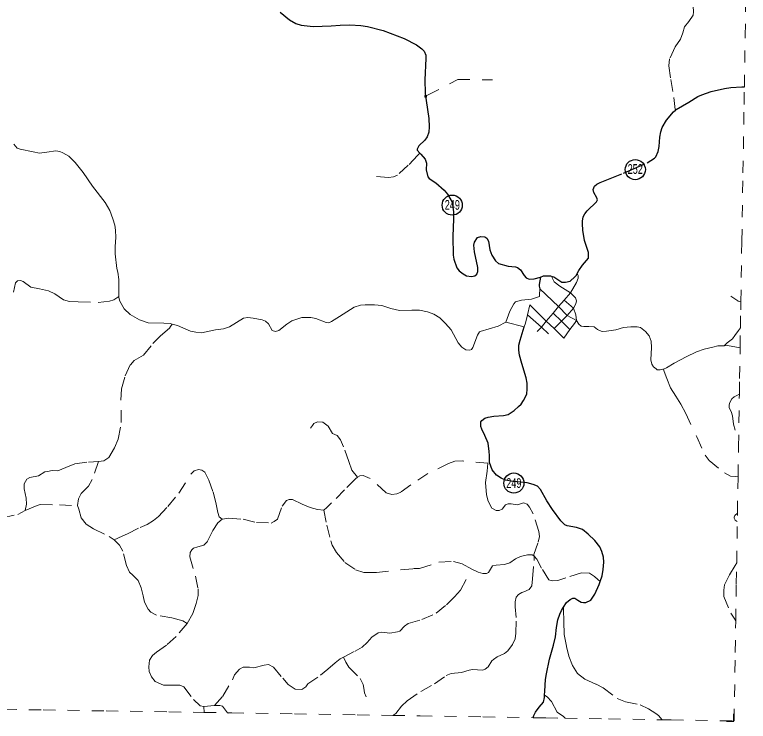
# Model space of a CAD drawing. Extents: x 703.1 to 728.9, y 7316.2 to 7344.3.
# Drawn here: x 722.52 to 728.57, y 7316.21 to 7322.04 of the extents above; entities that cross this region are included whole.
import ezdxf
from ezdxf.enums import TextEntityAlignment as Align

# ---------------------------------------------------------------- set-up
doc = ezdxf.new("R2010")
doc.units = 0
doc.header["$LTSCALE"] = 0.032
doc.header["$PDMODE"] = 32
doc.header["$PDSIZE"] = 0.016
for name, pattern in [('DOTTED', [1.5, 0.3, -1.2]), ('LONG_DASHED', [7.5, 6, -1.5]), ('MEDIUM_DASHED', [4.5, 3, -1.5]), ('SHORT_DASHED', [2.7, 1.5, -1.2])]:
    doc.linetypes.add(name, pattern=pattern)
for name, color, linetype, lineweight in [('13', 7, 'Continuous', 25), ('4', 7, 'LONG_DASHED', 25), ('5', 7, 'LONG_DASHED', 13), ('58', 7, 'SHORT_DASHED', 13), ('6', 7, 'MEDIUM_DASHED', 13), ('63', 7, 'Continuous', 25), ('7', 7, 'DOTTED', 13), ('8', 7, 'Continuous', 13)]:
    doc.layers.add(name, color=color, linetype=linetype, lineweight=lineweight)
doc.layers.add('61', color=7, linetype='Continuous')

msp = doc.modelspace()

# ---------------------------------------------------------------- linework, layer by layer
at = {"layer": '13'}
for centre in [(727.6388, 7320.7644), (726.1286, 7320.4714), (726.637, 7318.1783)]:
    msp.add_circle(centre, 0.083, dxfattribs=at)
at = {"layer": '4'}
for points in [[(724.7089, 7322.0645), (724.7865, 7321.9994), (724.839, 7321.9693), (724.8824, 7321.956), (724.9807, 7321.9455), (725.1304, 7321.9504), (725.2042, 7321.9566), (725.2825, 7321.9601), (725.3728, 7321.9545), (725.428, 7321.9441), (725.5591, 7321.9119), (725.7312, 7321.8461), (725.8344, 7321.7929), (725.8784, 7321.7607), (725.8959, 7321.7411), (725.9106, 7321.7089), (725.9106, 7321.6823), (725.9012, 7321.5038), (725.9057, 7321.3946), (725.909, 7321.3696)], [(727.9698, 7321.255), (727.9769, 7321.2608), (728.0818, 7321.3203), (728.1546, 7321.3665), (728.1875, 7321.3812), (728.2648, 7321.4078), (728.376, 7321.4337), (728.4278, 7321.4421), (728.5186, 7321.4467), (728.5387, 7321.4477)], [(725.909, 7321.3696), (725.9134, 7321.3358), (725.9354, 7321.1874), (725.9392, 7321.1167), (725.9344, 7321.074), (725.9204, 7321.0348), (725.9022, 7321.0075), (725.8529, 7320.9613), (725.8403, 7320.9326), (725.8403, 7320.9235), (725.8609, 7320.8998)], [(727.16, 7319.9085), (727.1724, 7319.9329), (727.2046, 7319.977), (727.2529, 7320.033), (727.2539, 7320.0799), (727.2211, 7320.1786), (727.2047, 7320.2647), (727.2019, 7320.3172), (727.2019, 7320.3403), (727.2082, 7320.3746), (727.2232, 7320.3991), (727.2428, 7320.425), (727.3177, 7320.4978), (727.3268, 7320.5139), (727.3219, 7320.5321), (727.2967, 7320.5769), (727.2915, 7320.6), (727.3026, 7320.6266), (727.3222, 7320.6434), (727.3488, 7320.6574), (727.5426, 7320.7351), (727.7367, 7320.8212), (727.7982, 7320.8576), (727.8077, 7320.8689), (727.8286, 7320.915), (727.837, 7320.9549), (727.8412, 7321.0319), (727.8506, 7321.0774), (727.8618, 7321.111), (727.8961, 7321.1726), (727.9528, 7321.2412), (727.9698, 7321.255)], [(725.8609, 7320.8998), (725.8683, 7320.8913), (725.906, 7320.8493), (725.9161, 7320.8171), (725.9119, 7320.7639), (725.928, 7320.7058), (725.9392, 7320.6911), (725.9917, 7320.6547), (726.0606, 7320.5959), (726.0893, 7320.5623), (726.1281, 7320.4965), (726.1386, 7320.4174), (726.14, 7320.3572), (726.132, 7320.2123), (726.1365, 7320.059), (726.1428, 7320.0247), (726.1662, 7319.9554), (726.1858, 7319.9281), (726.2194, 7319.9057), (726.246, 7319.8882), (726.2865, 7319.8819), (726.3159, 7319.8875), (726.3306, 7319.9029), (726.339, 7319.9225), (726.339, 7319.9575), (726.3117, 7320.0855), (726.3068, 7320.1401), (726.3117, 7320.166), (726.3362, 7320.2031), (726.3635, 7320.2136), (726.3963, 7320.2108), (726.4138, 7320.1982), (726.4285, 7320.1751), (726.4376, 7320.103), (726.454, 7320.0583), (726.4848, 7320.0114), (726.5114, 7319.989), (726.5904, 7319.968)], [(726.5904, 7319.968), (726.6492, 7319.9624), (726.6671, 7319.956), (726.6908, 7319.9379), (726.7216, 7319.891), (726.7391, 7319.8728), (726.7622, 7319.8616)], [(726.9532, 7319.8833), (726.9664, 7319.879), (727.0335, 7319.8363), (727.0629, 7319.8356), (727.1021, 7319.8454), (727.1392, 7319.879), (727.1528, 7319.8944), (727.16, 7319.9085)], [(726.7622, 7319.8616), (726.8035, 7319.8637), (726.8566, 7319.8777)], [(726.8566, 7319.8777), (726.8461, 7319.8174), (726.8447, 7319.8027), (726.8517, 7319.781)], [(726.8566, 7319.8777), (726.8804, 7319.8867), (726.9027, 7319.8888), (726.9405, 7319.8874), (726.9532, 7319.8833)], [(727.3491, 7317.3648), (727.3648, 7317.4137), (727.3734, 7317.4647), (727.3797, 7317.5253), (727.3752, 7317.5662), (727.3636, 7317.6137), (727.3472, 7317.6516), (727.3048, 7317.7046), (727.2503, 7317.7571), (727.2021, 7317.796), (727.1546, 7317.8121), (727.0764, 7317.8253), (727.0585, 7317.8349), (727.0252, 7317.8657), (726.956, 7317.9602), (726.9101, 7318.0324), (726.8566, 7318.1263), (726.8324, 7318.1516), (726.797, 7318.1657), (726.7456, 7318.1789), (726.6298, 7318.1905), (726.5667, 7318.2031), (726.5334, 7318.2183), (726.4943, 7318.2425), (726.4589, 7318.288), (726.4367, 7318.3476), (726.4359, 7318.4057), (726.4339, 7318.4385), (726.4241, 7318.5072), (726.3983, 7318.5713), (726.3726, 7318.6233), (726.3648, 7318.645), (726.3648, 7318.6824), (726.3713, 7318.695), (726.3976, 7318.7127), (726.4248, 7318.7223), (726.4723, 7318.7294), (726.5515, 7318.7354), (726.5906, 7318.743), (726.6401, 7318.7758), (726.6749, 7318.8091), (726.6966, 7318.8283), (726.7158, 7318.8586), (726.7428, 7318.9111), (726.7479, 7318.9561), (726.7463, 7319.002), (726.7395, 7319.0459), (726.7039, 7319.1656), (726.6845, 7319.2328), (726.6769, 7319.2737), (726.6787, 7319.3171), (726.6893, 7319.358), (726.7208, 7319.4661)], [(727.0464, 7317.1553), (727.0699, 7317.1941), (727.1002, 7317.2188), (727.1224, 7317.2274), (727.1391, 7317.2289), (727.1648, 7317.2112), (727.1916, 7317.1956), (727.2118, 7317.192), (727.232, 7317.193), (727.2721, 7317.2132), (727.3054, 7317.2612), (727.3413, 7317.3405), (727.3491, 7317.3648)], [(726.8898, 7316.4277), (726.8917, 7316.4618), (726.8975, 7316.5588), (726.9051, 7316.6042), (726.9321, 7316.7264), (726.9652, 7316.841), (726.9806, 7316.9102), (726.9892, 7316.9875), (726.9995, 7317.0486), (727.0157, 7317.0966), (727.0298, 7317.1279), (727.0464, 7317.1553)], [(726.7973, 7316.2424), (726.8013, 7316.2608), (726.815, 7316.2881), (726.8463, 7316.329), (726.8821, 7316.3714), (726.8887, 7316.4078), (726.8898, 7316.4277)]]:
    msp.add_lwpolyline(points, dxfattribs=at)
at = {"layer": '5'}
msp.add_line((726.5713, 7319.5053), (726.7208, 7319.4661), dxfattribs=at)
for points in [[(722.5107, 7320.974), (722.5386, 7320.9411), (722.5641, 7320.9321), (722.6708, 7320.9099), (722.7225, 7320.9), (722.7821, 7320.9082), (722.8576, 7320.9189), (722.8896, 7320.9148), (722.9159, 7320.9033), (722.966, 7320.8745), (723.0161, 7320.8228), (723.0838, 7320.7398), (723.1593, 7320.6289), (723.2652, 7320.4934), (723.303, 7320.426), (723.3268, 7320.3595), (723.3432, 7320.3061), (723.349, 7320.2659), (723.3535, 7320.2035), (723.3461, 7320.1287), (723.3477, 7320.0704), (723.3621, 7319.948), (723.3695, 7319.9193), (723.3769, 7319.8568), (723.3781, 7319.7336), (723.3781, 7319.7167)], [(726.5713, 7319.5053), (726.603, 7319.5957), (726.6358, 7319.6573), (726.6514, 7319.6737), (726.699, 7319.6868), (726.7836, 7319.695), (726.8473, 7319.7172), (726.8497, 7319.7279), (726.8517, 7319.781)], [(723.3781, 7319.7167), (723.3781, 7319.7081), (723.3863, 7319.6786), (723.422, 7319.6162), (723.4712, 7319.5694), (723.5468, 7319.5242), (723.619, 7319.5004), (723.7479, 7319.4979), (723.8017, 7319.4938), (723.8162, 7319.4902)], [(723.8162, 7319.4902), (723.8617, 7319.479), (723.9684, 7319.4314), (724.0128, 7319.4232), (724.0591, 7319.419), (724.1757, 7319.4437), (724.2414, 7319.4511), (724.2915, 7319.4683), (724.4056, 7319.539), (724.443, 7319.5439), (724.4857, 7319.539), (724.5588, 7319.5242), (724.5875, 7319.5127), (724.6122, 7319.4914), (724.6425, 7319.438), (724.6713, 7319.4298), (724.6967, 7319.4363), (724.7624, 7319.4881), (724.8039, 7319.5177), (724.8877, 7319.5431), (724.9607, 7319.5456), (725.0026, 7319.5349), (725.0872, 7319.5029), (725.111, 7319.5004), (725.1312, 7319.5103), (725.1993, 7319.553), (725.32, 7319.6302), (725.3709, 7319.645), (725.4099, 7319.6491), (725.4863, 7319.6491), (725.5487, 7319.6433), (725.6209, 7319.6179), (725.694, 7319.6022), (725.7958, 7319.6055), (725.8578, 7319.6039), (725.9235, 7319.5899), (725.9777, 7319.5726), (726.0262, 7319.5406), (726.0738, 7319.4946), (726.1193, 7319.4412), (726.1776, 7319.3352), (726.208, 7319.2991), (726.2417, 7319.2786), (726.2737, 7319.2753), (726.286, 7319.2802), (726.2983, 7319.2975), (726.3381, 7319.3985), (726.3545, 7319.4248), (726.3578, 7319.4281), (726.5081, 7319.4732), (726.5713, 7319.5053)], [(727.8704, 7319.1191), (727.8649, 7319.1169), (727.8453, 7319.1118), (727.8207, 7319.1137), (727.81, 7319.12), (727.7886, 7319.137), (727.7744, 7319.1597), (727.7681, 7319.1957), (727.7732, 7319.2966), (727.7697, 7319.3483), (727.7527, 7319.3918), (727.7243, 7319.4284), (727.6811, 7319.4612), (727.6534, 7319.4662), (727.601, 7319.4669), (727.5424, 7319.4606), (727.4775, 7319.4429), (727.4003, 7319.4328), (727.37, 7319.4284), (727.3561, 7319.4315), (727.3284, 7319.4461), (727.3, 7319.4669), (727.2565, 7319.4707), (727.236, 7319.4694), (727.2139, 7319.4688), (727.1931, 7319.4732), (727.1736, 7319.4903), (727.1544, 7319.5201)], [(728.3726, 7319.3113), (728.3198, 7319.3093), (728.2776, 7319.3004), (728.2069, 7319.2834), (728.1439, 7319.2613), (728.06, 7319.2203), (727.9594, 7319.1679), (727.8976, 7319.1301), (727.8704, 7319.1191)], [(728.504, 7319.2946), (728.3999, 7319.3124), (728.3726, 7319.3113)]]:
    msp.add_lwpolyline(points, dxfattribs=at)
at = {"layer": '58'}
for points in [[(728.5387, 7321.4477), (728.5454, 7321.8676), (728.5545, 7322.4328), (728.5636, 7322.998), (728.5716, 7323.4937)], [(728.5101, 7319.6735), (728.5181, 7320.1721), (728.5272, 7320.7372), (728.5363, 7321.3024), (728.5387, 7321.4477)], [(728.5066, 7319.458), (728.509, 7319.6069), (728.5101, 7319.6735)], [(728.4978, 7318.9127), (728.4999, 7319.0417), (728.504, 7319.2946), (728.5066, 7319.458)], [(728.4868, 7318.2306), (728.4908, 7318.4765), (728.4978, 7318.9127)], [(728.4754, 7317.5201), (728.4817, 7317.9113), (728.482, 7317.9307), (728.4868, 7318.2306)], [(728.4676, 7317.0418), (728.4726, 7317.3461), (728.4754, 7317.5201)], [(728.4543, 7316.2158), (728.4634, 7316.781), (728.4676, 7317.0418)], [(719.8371, 7316.3522), (720.163, 7316.3471), (720.6812, 7316.3391), (721.1994, 7316.331), (721.7176, 7316.3229), (722.2358, 7316.3147), (722.754, 7316.3066), (723.2722, 7316.2984), (723.7904, 7316.2903), (724.081, 7316.2857), (724.2752, 7316.2826)], [(724.2752, 7316.2826), (724.3086, 7316.2821), (724.8268, 7316.2738), (725.345, 7316.2656), (725.637, 7316.2609)], [(725.637, 7316.2609), (725.8633, 7316.2573), (726.3815, 7316.2491), (726.7973, 7316.2424)], [(726.7973, 7316.2424), (726.8997, 7316.2408), (727.059, 7316.2382)], [(727.059, 7316.2382), (727.4179, 7316.2325), (727.8616, 7316.2253)], [(727.8616, 7316.2253), (727.9361, 7316.2241), (728.4543, 7316.2158)]]:
    msp.add_lwpolyline(points, dxfattribs=at)
at = {"layer": '6'}
for points in [[(727.8821, 7322.5301), (727.8963, 7322.5053), (727.9161, 7322.4836), (727.9701, 7322.4267), (728.0443, 7322.3032), (728.0863, 7322.2014), (728.1171, 7322.1126), (728.12, 7322.0673), (728.1161, 7322.0374), (728.0809, 7321.9877), (728.0462, 7321.9414), (728.0317, 7321.8941), (728.0124, 7321.8411), (727.969, 7321.7774), (727.9222, 7321.6785), (727.9145, 7321.6216), (727.9319, 7321.5068), (727.9565, 7321.3587), (727.9698, 7321.255)], [(722.5078, 7319.753), (722.5253, 7319.8309), (722.5421, 7319.847), (722.5665, 7319.8493), (722.5879, 7319.8401), (722.6498, 7319.7958), (722.7223, 7319.7805), (722.7967, 7319.7641), (722.8486, 7319.7389), (722.9196, 7319.69), (722.9707, 7319.6755), (723.0425, 7319.6732), (723.2055, 7319.6682), (723.3002, 7319.6797), (723.3361, 7319.6896), (723.3781, 7319.7167)], [(723.2089, 7318.3555), (723.253, 7318.3607), (723.2934, 7318.3903), (723.3417, 7318.4681), (723.3722, 7318.541), (723.3968, 7318.679), (723.3944, 7318.8618), (723.3988, 7318.9569), (723.4283, 7319.0624), (723.4722, 7319.1536), (723.5037, 7319.1881), (723.5796, 7319.2334), (723.6584, 7319.33), (723.7219, 7319.3936), (723.7948, 7319.4557), (723.8038, 7319.4702), (723.8162, 7319.4902)], [(722.6057, 7317.9514), (722.6146, 7318.0051), (722.6124, 7318.0533), (722.5956, 7318.1294), (722.5967, 7318.1719), (722.6175, 7318.2105), (722.6432, 7318.224), (722.7148, 7318.2374), (722.7663, 7318.271), (722.7875, 7318.2743), (722.8278, 7318.2811), (722.8737, 7318.2788), (722.9397, 7318.3068), (723.0153, 7318.3365), (723.1272, 7318.351), (723.2089, 7318.3555)], [(723.2089, 7318.3555), (723.1574, 7318.2088), (723.1272, 7318.1517), (723.0668, 7318.0913), (723.0433, 7318.0487), (723.0349, 7317.9922)], [(726.8048, 7317.5741), (726.8013, 7317.5891), (726.8373, 7317.6912), (726.8483, 7317.7365), (726.8439, 7317.7796), (726.7973, 7317.9231), (726.767, 7317.9807), (726.7476, 7318.0054), (726.7177, 7318.0159), (726.6676, 7317.9992), (726.6139, 7318.0062), (726.5893, 7318.0062), (726.5673, 7317.9983), (726.5409, 7317.9622), (726.5162, 7317.9525), (726.4916, 7317.9525), (726.4564, 7317.9719), (726.4247, 7318.03), (726.4115, 7318.0819), (726.4041, 7318.1819), (726.4159, 7318.2756), (726.423, 7318.3434), (726.2144, 7318.361), (726.1493, 7318.3592), (726.0983, 7318.3407), (725.928, 7318.2576), (725.7876, 7318.1638), (725.704, 7318.1031), (725.6706, 7318.0907), (725.631, 7318.0837), (725.5826, 7318.0987), (725.4501, 7318.2162), (725.3938, 7318.2399), (725.3648, 7318.2373), (725.347, 7318.2256)], [(723.3398, 7317.7094), (723.4036, 7317.7408), (723.4494, 7317.7598), (723.5535, 7317.8124), (723.6106, 7317.8371), (723.6643, 7317.8695), (723.7057, 7317.9031), (723.7823, 7317.9843), (723.8729, 7318.0962), (723.972, 7318.2513), (723.9988, 7318.2781), (724.0335, 7318.2905), (724.0626, 7318.2837), (724.0872, 7318.2669), (724.1186, 7318.2009), (724.1555, 7318.1024), (724.1773, 7318.0179), (724.1941, 7317.935), (724.2064, 7317.8992), (724.231, 7317.8802)], [(725.347, 7318.2256), (725.3291, 7318.2139), (725.2402, 7318.1224), (725.1329, 7318.0141), (725.0928, 7317.9759), (725.0699, 7317.9547)], [(724.231, 7317.8802), (724.2854, 7317.8897), (724.4029, 7317.8791), (724.5133, 7317.8533), (724.6331, 7317.8486), (724.6601, 7317.8615), (724.6859, 7317.8791), (724.7247, 7317.9884), (724.7599, 7318.0331), (724.7834, 7318.0425), (724.8105, 7318.0437), (724.8892, 7318.0037), (724.9573, 7317.9767), (725.0172, 7317.959), (725.0699, 7317.9547)], [(722.6057, 7317.9514), (722.6902, 7317.9888), (722.7294, 7318), (722.8871, 7317.9989), (723.0349, 7317.9922)], [(723.0349, 7317.9922), (723.0472, 7317.9619), (723.0673, 7317.8925), (723.1087, 7317.8399), (723.1691, 7317.8018), (723.2984, 7317.7385), (723.3398, 7317.7094)], [(725.0699, 7317.9547), (725.0946, 7317.8297), (725.1275, 7317.7026), (725.1381, 7317.6647), (725.1724, 7317.6066), (725.2424, 7317.5235), (725.3313, 7317.4619), (725.3999, 7317.4407), (725.5037, 7317.4407), (725.8095, 7317.472), (725.8593, 7317.4742), (726.0185, 7317.5243), (726.1399, 7317.5322), (726.209, 7317.5116), (726.2909, 7317.4684)], [(722.4166, 7317.8909), (722.543, 7317.9189), (722.5755, 7317.9346), (722.6057, 7317.9514)], [(724.231, 7317.8802), (724.1946, 7317.8494), (724.1543, 7317.7878), (724.1095, 7317.6971), (724.0793, 7317.6658), (724.0279, 7317.6524), (723.9943, 7317.6412), (723.9791, 7317.6283), (723.9657, 7317.6048), (723.9624, 7317.5701), (724.0094, 7317.4111), (724.0312, 7317.3042), (724.0323, 7317.2504), (724.0166, 7317.1833), (723.9881, 7317.1021), (723.94, 7317.0204)], [(723.94, 7317.0204), (723.9064, 7317.0417), (723.8158, 7317.0663), (723.6893, 7317.0876), (723.6401, 7317.1133), (723.62, 7317.1368), (723.5897, 7317.1962), (723.5774, 7317.2466), (723.5607, 7317.3126), (723.5366, 7317.3736), (723.4918, 7317.4184), (723.4661, 7317.4442), (723.4415, 7317.499), (723.409, 7317.6155), (723.3839, 7317.6653), (723.3398, 7317.7094)], [(726.2909, 7317.4684), (726.343, 7317.4437), (726.3802, 7317.4307), (726.4114, 7317.4307), (726.4279, 7317.4403), (726.4617, 7317.494), (726.4903, 7317.5018), (726.5596, 7317.5053), (726.6047, 7317.52), (726.6506, 7317.5539), (726.6904, 7317.5729), (726.7494, 7317.5868), (726.7884, 7317.5859), (726.8048, 7317.5741)], [(726.7191, 7317.2802), (726.7632, 7317.2988), (726.7855, 7317.3302), (726.7905, 7317.3891), (726.8047, 7317.5392), (726.8048, 7317.5741)], [(727.3491, 7317.3648), (727.3291, 7317.383), (727.3033, 7317.4064), (727.261, 7317.4337), (727.1942, 7317.4372), (727.0666, 7317.3976), (726.9988, 7317.3747), (726.954, 7317.3712), (726.9258, 7317.3791), (726.8651, 7317.4768), (726.8259, 7317.5495), (726.8048, 7317.5741)], [(725.2314, 7316.7429), (725.3263, 7316.7926), (725.3838, 7316.8246), (725.4265, 7316.8616), (725.4663, 7316.9071), (725.5175, 7316.9412), (725.5474, 7316.9469), (725.6142, 7316.9384), (725.6754, 7316.9498), (725.6967, 7316.9569), (725.7351, 7316.9967), (725.7636, 7317.0195), (725.8774, 7317.0522), (725.9961, 7317.1042), (726.0814, 7317.1725), (726.1483, 7317.2394), (726.1973, 7317.2941), (726.2909, 7317.4684)], [(725.637, 7316.2609), (725.6627, 7316.2775), (725.7085, 7316.3364), (725.7565, 7316.3816), (725.8681, 7316.459), (725.9831, 7316.5213), (726.0772, 7316.5895), (726.1197, 7316.608), (726.2046, 7316.6162), (726.2676, 7316.6333), (726.2953, 7316.6392), (726.3768, 7316.6351), (726.4008, 7316.6419), (726.4254, 7316.6631), (726.4555, 7316.7104), (726.4699, 7316.7234), (726.5, 7316.744), (726.5592, 7316.7731), (726.5866, 7316.7943), (726.6249, 7316.845), (726.6482, 7316.8943), (726.6533, 7316.9398), (726.6554, 7317.0699), (726.6482, 7317.1566), (726.6475, 7317.1977), (726.6571, 7317.2381), (726.6759, 7317.2576), (726.7013, 7317.274), (726.7191, 7317.2802)], [(727.0464, 7317.1553), (727.0467, 7317.1353), (727.048, 7317.0321), (727.0513, 7316.9297), (727.0705, 7316.8309), (727.0914, 7316.7499), (727.1212, 7316.6733), (727.1627, 7316.6079), (727.2225, 7316.5604), (727.3156, 7316.5183), (727.3732, 7316.488), (727.4895, 7316.4012), (727.5571, 7316.3736), (727.6784, 7316.348), (727.7472, 7316.3143), (727.8078, 7316.2759), (727.8306, 7316.2597), (727.8616, 7316.2253)], [(723.94, 7317.0204), (723.8507, 7316.9129), (723.7696, 7316.8403), (723.6886, 7316.7834), (723.6546, 7316.7559), (723.6312, 7316.7166), (723.626, 7316.661), (723.6288, 7316.6226), (723.6459, 7316.5799), (723.6772, 7316.5401), (723.7469, 7316.5102), (723.8379, 7316.5102), (723.8806, 7316.5102), (723.9133, 7316.496), (723.9937, 7316.3913), (724.0477, 7316.3415), (724.0776, 7316.3358), (724.1657, 7316.3429)], [(724.1657, 7316.3429), (724.2354, 7316.4198), (724.3151, 7316.555), (724.3307, 7316.5948), (724.372, 7316.6432), (724.4033, 7316.6603), (724.4545, 7316.6588), (724.49, 7316.6546), (724.5768, 7316.6745), (724.613, 7316.6809), (724.6543, 7316.6595), (724.7296, 7316.5684), (724.7759, 7316.5165), (724.8328, 7316.4767), (724.8868, 7316.4752), (724.9209, 7316.498), (724.938, 7316.5208), (725.0404, 7316.5919), (725.103, 7316.6417), (725.1613, 7316.6958), (725.204, 7316.7285), (725.2314, 7316.7429)], [(724.1657, 7316.3429), (724.2113, 7316.3443), (724.234, 7316.3372), (724.2752, 7316.2826), (724.2781, 7316.2788)]]:
    msp.add_lwpolyline(points, dxfattribs=at)
at = {"layer": '63'}
msp.add_lwpolyline([(728.3914, 7316.2124), (728.453, 7316.2124), (728.453, 7316.2731)], dxfattribs=at)
at = {"layer": '7'}
for points in [[(725.909, 7321.3696), (725.929, 7321.3801), (726.1748, 7321.5088), (726.4617, 7321.5047)], [(725.8609, 7320.8998), (725.8417, 7320.8798), (725.7653, 7320.8003), (725.6761, 7320.7184), (725.645, 7320.7045), (725.6024, 7320.6996), (725.4108, 7320.7168)], [(728.5101, 7319.6735), (728.4891, 7319.6802), (728.4839, 7319.6819), (728.4267, 7319.7209)], [(728.5066, 7319.458), (728.4912, 7319.4366), (728.4609, 7319.3945), (728.4418, 7319.369), (728.3981, 7319.3362), (728.3726, 7319.3113)], [(727.8704, 7319.1191), (727.8778, 7319.0991), (727.8998, 7319.0398), (727.9299, 7318.9641), (727.9729, 7318.8961), (728.0142, 7318.829), (728.0555, 7318.7525), (728.1471, 7318.5585), (728.2146, 7318.4075), (728.2473, 7318.3645), (728.3759, 7318.2626), (728.4249, 7318.2342), (728.4668, 7318.2318), (728.4868, 7318.2306)], [(728.4978, 7318.9127), (728.4768, 7318.9019), (728.4534, 7318.8898), (728.4345, 7318.8726), (728.4182, 7318.8416), (728.4122, 7318.8227), (728.4147, 7318.7986), (728.4311, 7318.7694), (728.4423, 7318.7332), (728.4491, 7318.6644), (728.4637, 7318.6137)], [(725.347, 7318.2256), (725.2995, 7318.286), (725.2753, 7318.3567), (725.2321, 7318.4759), (725.2068, 7318.535), (725.1783, 7318.5708), (725.1403, 7318.5867), (725.1034, 7318.6479), (725.0613, 7318.6795), (725.0159, 7318.6848), (724.9875, 7318.6689), (724.9748, 7318.6521), (724.96, 7318.632)], [(728.482, 7317.9307), (728.461, 7317.9116), (728.4592, 7317.91), (728.4554, 7317.8963), (728.4554, 7317.888), (728.4637, 7317.8725), (728.4799, 7317.8616)], [(728.4754, 7317.5201), (728.4621, 7317.4983), (728.4158, 7317.4224), (728.3762, 7317.3384), (728.3688, 7317.2933), (728.3688, 7317.2416), (728.4278, 7317.106), (728.4543, 7317.0633), (728.4676, 7317.0418)], [(725.2314, 7316.7429), (725.2495, 7316.6992), (725.2759, 7316.66), (725.3677, 7316.5661), (725.3927, 7316.5154), (725.4002, 7316.487), (725.4042, 7316.4465), (725.4184, 7316.4154)], [(726.8898, 7316.4277), (726.9129, 7316.4147), (726.9472, 7316.3757), (726.9953, 7316.2887), (727.0472, 7316.2513), (727.059, 7316.2382)], [(724.0776, 7316.3358), (724.081, 7316.2857), (724.0813, 7316.2818)]]:
    msp.add_lwpolyline(points, dxfattribs=at)
msp.add_point((725.909, 7321.3696), dxfattribs=at)
at = {"layer": '8'}
for p, q in [((727.0059, 7319.6351), (726.8517, 7319.781)), ((727.0529, 7319.6879), (727.1033, 7319.7487)), ((726.8649, 7319.4654), (726.9027, 7319.5135)), ((726.8649, 7319.4654), (726.9222, 7319.4092))]:
    msp.add_line(p, q, dxfattribs=at)
for points in [[(727.1033, 7319.7487), (727.1549, 7319.8324), (727.1664, 7319.868), (727.1664, 7319.8909), (727.16, 7319.9085)], [(727.1033, 7319.7487), (727.0162, 7319.8014), (726.9704, 7319.8381), (726.9543, 7319.8702), (726.9532, 7319.8833)], [(727.1033, 7319.7487), (727.1446, 7319.7062), (727.1526, 7319.681), (727.148, 7319.6581), (727.1286, 7319.6225)], [(727.0059, 7319.6351), (727.0529, 7319.6879), (727.1286, 7319.6225)], [(726.9027, 7319.5135), (726.7674, 7319.6477), (726.7502, 7319.5675)], [(726.96, 7319.5801), (727.0059, 7319.6351), (727.0781, 7319.5606), (727.03, 7319.5147)], [(727.1544, 7319.5201), (727.148, 7319.5675), (727.1286, 7319.6225), (727.0781, 7319.5606)], [(726.7208, 7319.4661), (726.7319, 7319.4975), (726.7502, 7319.5675), (726.8649, 7319.4654), (726.8305, 7319.4275)], [(726.9027, 7319.5135), (726.96, 7319.5801), (727.03, 7319.5147)], [(727.0999, 7319.4447), (727.1377, 7319.4952), (727.1544, 7319.5201), (727.0781, 7319.5606)], [(726.9027, 7319.5135), (726.9692, 7319.4539), (727.03, 7319.5147), (727.0999, 7319.4447)], [(727.0999, 7319.4447), (727.0506, 7319.3748), (726.9692, 7319.4539)]]:
    msp.add_lwpolyline(points, dxfattribs=at)

# ---------------------------------------------------------------- texts
at = {"layer": '61', "width": 0.7}
for s, p in [('252', (727.6386, 7320.7294)), ('249', (726.1291, 7320.4332)), ('249', (726.6368, 7318.1382))]:
    msp.add_text(s, height=0.08, dxfattribs=at).set_placement(p, align=Align.CENTER)

doc.saveas('drawing.dxf')
